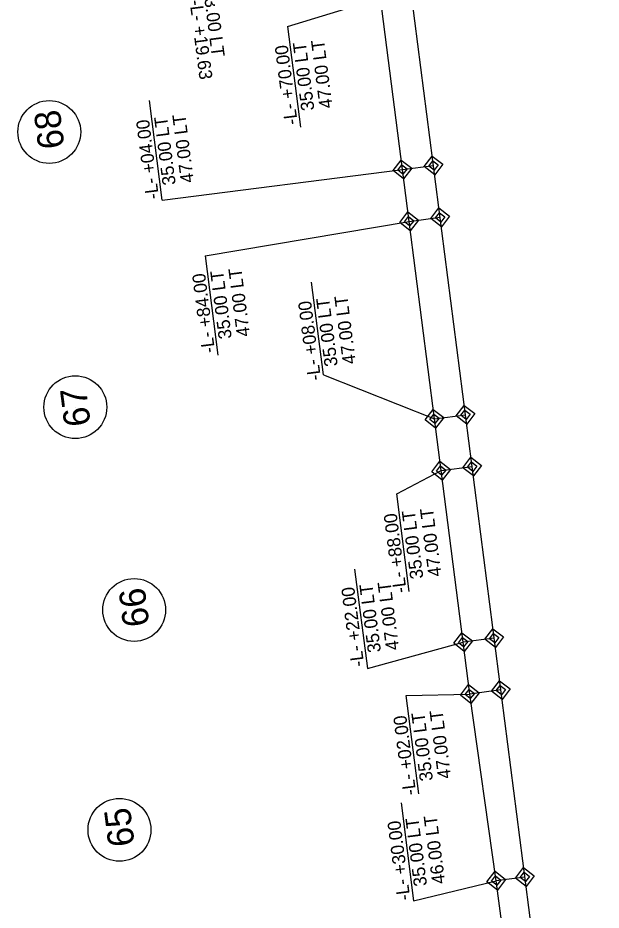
# Model space of a CAD drawing. Extents: x 2368169 to 2369183, y 801414 to 808542.
# Drawn here: x 2368258.4 to 2368481, y 807120.4 to 807461.2 of the extents above; entities that cross this region are included whole.
import ezdxf

# ---------------------------------------------------------------- set-up
doc = ezdxf.new("R2010")
doc.units = 0
for name, color, linetype in [('Prop Easement Construction', 7, 'Continuous'), ('Prop Easement Construction Station Offsets', 7, 'Continuous'), ('Prop Easement Permanent Drainage Utility', 7, 'Continuous'), ('Prop Easement Permanent Drainage Utility Station Offsets', 7, 'Continuous'), ('Prop Parcel Number CELL', 7, 'Continuous'), ('Prop Parcel Number Text', 7, 'Continuous'), ('Prop ROW Permanent Easement CELL', 7, 'Continuous'), ('Prop ROW RW Lines', 7, 'Continuous')]:
    doc.layers.add(name, color=color, linetype=linetype)

msp = doc.modelspace()

# ---------------------------------------------------------------- linework, layer by layer
at = {"layer": 'Prop Easement Construction'}
for p, q in [((2368405.17, 807403.33), (2368396.77, 807468.79)), ((2368417.38, 807308.11), (2368407.71, 807383.49)), ((2368428.32, 807222.81), (2368419.93, 807288.27)), ((2368441.02, 807131.68), (2368430.87, 807202.97))]:
    msp.add_line(p, q, dxfattribs=at)
at = {"layer": 'Prop Easement Permanent Drainage Utility'}
for p, q in [((2368405.17, 807403.33), (2368417.07, 807404.86)), ((2368407.71, 807383.49), (2368405.17, 807403.33)), ((2368407.71, 807383.49), (2368419.62, 807385.02)), ((2368417.38, 807308.11), (2368429.28, 807309.64)), ((2368419.93, 807288.27), (2368417.38, 807308.11)), ((2368419.93, 807288.27), (2368431.83, 807289.8)), ((2368440.23, 807224.33), (2368428.32, 807222.81)), ((2368430.87, 807202.97), (2368428.32, 807222.81)), ((2368442.77, 807204.5), (2368430.87, 807202.97)), ((2368451.93, 807133.08), (2368441.02, 807131.68)), ((2368443.56, 807111.84), (2368441.02, 807131.68))]:
    msp.add_line(p, q, dxfattribs=at)
at = {"layer": 'Prop Easement Permanent Drainage Utility Station Offsets'}
for p, q in [((2368361.38, 807457.88), (2368396.77, 807468.79)), ((2368361.38, 807457.88), (2368366.29, 807419.44)), ((2368313.53, 807391.59), (2368308.67, 807429.65)), ((2368313.53, 807391.59), (2368405.17, 807403.33)), ((2368329.9, 807370.29), (2368407.71, 807383.49)), ((2368329.9, 807370.29), (2368334.74, 807332.33)), ((2368375.02, 807324.88), (2368370.5, 807360.29)), ((2368375.02, 807324.88), (2368417.38, 807308.11))]:
    msp.add_line(p, q, dxfattribs=at)
for points in [[(2368407.81, 807242.1), (2368403.06, 807279.36), (2368419.93, 807288.27)], [(2368386.95, 807250.62), (2368391.8, 807212.66), (2368428.32, 807222.81)], [(2368411.47, 807164.89), (2368406.68, 807202.4), (2368430.87, 807202.97)], [(2368404.69, 807161.38), (2368409.46, 807124.03), (2368441.02, 807131.68)]]:
    msp.add_lwpolyline(points, dxfattribs=at)
at = {"layer": 'Prop Parcel Number CELL'}
for p, q in [((2368270.41, 807417.61), (2368270.41, 807417.61)), ((2368280.34, 807312.53), (2368280.34, 807312.53)), ((2368302.81, 807235.06), (2368302.81, 807235.06)), ((2368297.18, 807151.1), (2368297.18, 807151.1))]:
    msp.add_line(p, q, dxfattribs=at)
for centre in [(2368270.41, 807417.61), (2368280.34, 807312.53), (2368302.81, 807235.06), (2368297.18, 807151.1)]:
    msp.add_circle(centre, 12, dxfattribs=at)
at = {"layer": 'Prop ROW Permanent Easement CELL'}
for p, q in [((2368417.07, 807404.86), (2368417.07, 807404.86)), ((2368405.17, 807403.33), (2368405.17, 807403.33)), ((2368407.71, 807383.49), (2368407.71, 807383.49)), ((2368419.62, 807385.02), (2368419.62, 807385.02)), ((2368429.28, 807309.64), (2368429.28, 807309.64)), ((2368417.38, 807308.11), (2368417.38, 807308.11)), ((2368419.93, 807288.27), (2368419.93, 807288.27)), ((2368431.83, 807289.8), (2368431.83, 807289.8)), ((2368440.23, 807224.33), (2368440.23, 807224.33)), ((2368428.32, 807222.81), (2368428.32, 807222.81)), ((2368430.87, 807202.97), (2368430.87, 807202.97)), ((2368442.77, 807204.5), (2368442.77, 807204.5)), ((2368441.02, 807131.68), (2368441.02, 807131.68)), ((2368451.93, 807133.08), (2368451.93, 807133.08))]:
    msp.add_line(p, q, dxfattribs=at)
for points in [[(2368417.55, 807401.29), (2368413.5, 807404.38), (2368416.6, 807408.42), (2368420.64, 807405.33)], [(2368405.64, 807399.76), (2368401.6, 807402.86), (2368404.7, 807406.9), (2368408.74, 807403.8)], [(2368405.41, 807401.54), (2368403.39, 807403.09), (2368404.93, 807405.11), (2368406.95, 807403.57)], [(2368417.31, 807403.07), (2368415.29, 807404.62), (2368416.84, 807406.64), (2368418.86, 807405.09)], [(2368408.19, 807379.92), (2368404.15, 807383.02), (2368407.24, 807387.06), (2368411.28, 807383.96)], [(2368420.09, 807381.45), (2368416.05, 807384.55), (2368419.14, 807388.59), (2368423.19, 807385.49)], [(2368407.95, 807381.71), (2368405.93, 807383.25), (2368407.48, 807385.28), (2368409.5, 807383.73)], [(2368419.85, 807383.23), (2368417.83, 807384.78), (2368419.38, 807386.8), (2368421.4, 807385.25)], [(2368429.76, 807306.07), (2368425.72, 807309.16), (2368428.81, 807313.2), (2368432.85, 807310.11)], [(2368417.85, 807304.54), (2368413.81, 807307.64), (2368416.91, 807311.68), (2368420.95, 807308.58)], [(2368417.62, 807306.33), (2368415.6, 807307.87), (2368417.15, 807309.89), (2368419.17, 807308.35)], [(2368429.52, 807307.85), (2368427.5, 807309.4), (2368429.05, 807311.42), (2368431.07, 807309.87)], [(2368420.4, 807284.7), (2368416.36, 807287.8), (2368419.45, 807291.84), (2368423.5, 807288.74)], [(2368432.3, 807286.23), (2368428.26, 807289.33), (2368431.36, 807293.37), (2368435.4, 807290.27)], [(2368432.07, 807288.01), (2368430.04, 807289.56), (2368431.59, 807291.58), (2368433.61, 807290.03)], [(2368420.16, 807286.49), (2368418.14, 807288.04), (2368419.69, 807290.06), (2368421.71, 807288.51)], [(2368440.7, 807220.77), (2368436.66, 807223.86), (2368439.75, 807227.9), (2368443.79, 807224.81)], [(2368428.79, 807219.24), (2368424.75, 807222.34), (2368427.85, 807226.38), (2368431.89, 807223.28)], [(2368428.56, 807221.02), (2368426.54, 807222.57), (2368428.09, 807224.59), (2368430.11, 807223.04)], [(2368440.46, 807222.55), (2368438.44, 807224.1), (2368439.99, 807226.12), (2368442.01, 807224.57)], [(2368431.34, 807199.4), (2368427.3, 807202.5), (2368430.39, 807206.54), (2368434.44, 807203.44)], [(2368443.24, 807200.93), (2368439.2, 807204.02), (2368442.3, 807208.06), (2368446.34, 807204.97)], [(2368443.01, 807202.71), (2368440.98, 807204.26), (2368442.53, 807206.28), (2368444.55, 807204.73)], [(2368431.1, 807201.19), (2368429.08, 807202.73), (2368430.63, 807204.75), (2368432.65, 807203.21)], [(2368441.49, 807128.11), (2368437.45, 807131.21), (2368440.55, 807135.25), (2368444.59, 807132.15)], [(2368452.4, 807129.51), (2368448.36, 807132.61), (2368451.46, 807136.65), (2368455.5, 807133.55)], [(2368452.16, 807131.3), (2368450.14, 807132.85), (2368451.69, 807134.87), (2368453.71, 807133.32)], [(2368441.25, 807129.9), (2368439.23, 807131.45), (2368440.78, 807133.47), (2368442.8, 807131.92)]]:
    msp.add_lwpolyline(points, close=True, dxfattribs=at)
at = {"layer": 'Prop ROW RW Lines'}
msp.add_line((2368481.04, 806906.1), (2368402.36, 807519.55), dxfattribs=at)

# ---------------------------------------------------------------- texts
at = {"layer": 'Prop Easement Construction Station Offsets'}
for s, p in [('43.00 LT', (2368329.11, 807472.23)), ('-L- +19.63', (2368323.91, 807467.8))]:
    msp.add_text(s, height=5, rotation=277.2784, dxfattribs=at).set_placement(p)
at = {"layer": 'Prop Easement Permanent Drainage Utility Station Offsets'}
for s, p in [('47.00 LT', (2368378.57, 807426.93)), ('-L- +70.00', (2368365.26, 807420.65)), ('35.00 LT', (2368371.63, 807426.04)), ('-L- +04.00', (2368312.32, 807392.21)), ('35.00 LT', (2368318.69, 807397.6)), ('47.00 LT', (2368325.63, 807398.49)), ('-L- +84.00', (2368333.72, 807333.47)), ('35.00 LT', (2368340.09, 807338.86)), ('47.00 LT', (2368347.03, 807339.75)), ('-L- +08.00', (2368374.16, 807322.96)), ('35.00 LT', (2368380.53, 807328.34)), ('47.00 LT', (2368387.47, 807329.23)), ('-L- +88.00', (2368406.84, 807241.82)), ('35.00 LT', (2368413.21, 807247.21)), ('47.00 LT', (2368420.15, 807248.1)), ('35.00 LT', (2368397.02, 807219.09)), ('47.00 LT', (2368403.97, 807219.98)), ('-L- +22.00', (2368390.65, 807213.7)), ('47.00 LT', (2368423.81, 807170.9)), ('-L- +02.00', (2368410.5, 807164.62)), ('35.00 LT', (2368416.87, 807170.01)), ('35.00 LT', (2368414.61, 807129.83)), ('46.00 LT', (2368421.56, 807130.72)), ('-L- +30.00', (2368408.25, 807124.44))]:
    msp.add_text(s, height=5, rotation=97.2784, dxfattribs=at).set_placement(p)
at = {"layer": 'Prop Parcel Number Text'}
for s, p in [('68', (2368276.26, 807411.76)), ('67', (2368286.24, 807305.77)), ('66', (2368308.65, 807229.25)), ('65', (2368303.03, 807145.28))]:
    msp.add_text(s, height=10, rotation=97.2784, dxfattribs=at).set_placement(p)

doc.saveas('drawing.dxf')
